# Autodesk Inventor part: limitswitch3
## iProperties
Shininess: 0.0
Created: 2002-01
Part Number: limitswitch3
Document SubType Name: Modeling
Density: 1 g/cm^3
Density: 0.0
Volumn: 0.0
Area: 0.0
PropertySet Name: Model Information
Control State: 0
Master: False
Checked Out: False
Author: Administrator
